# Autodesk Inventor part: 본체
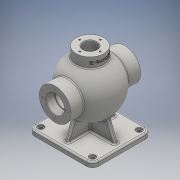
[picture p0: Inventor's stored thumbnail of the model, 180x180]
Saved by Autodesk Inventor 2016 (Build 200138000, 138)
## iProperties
Created: 2017-01
Part Number: 본체
Material: 일반
Document SubType Name: Modeling
Designer: Administrator
Density: 1 g/cm^3
Appearance: 기본값
Author: Administrator
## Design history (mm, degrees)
sketch "스케치1"
  geometry: L1 (-62.5, 57.5)-(62.5, 57.5); L2 (62.5, 57.5)-(62.5, -57.5); L3 (62.5, -57.5)-(-62.5, -57.5); L4 (-62.5, -57.5)-(-62.5, 57.5); 1 further point
  constraints: 8 end point, 2 parallel, 1 horizontal, 1 perpendicular
  dimensions: "d0" = 125 distance of L1.start L1.end; "d1" = 115 distance of L1.end L2.end; "d2" = 57.5 distance from line of point (0, 0) L1; "d3" = 62.5 distance from line of point (0, 0) L4
extrude "돌출1" new body sketch "스케치1" distance "d4" = 10; taper "d5" = 0 deg
fillet "모깎기1" dims "d6" = 12
sketch "스케치2"
  geometry: A1 r 12 centre (-50.5, 45.5) between (-50.5, 57.5) and (-62.5, 45.5) reference; 2 further points
  constraints: 1 coincident
hole "구멍1" sketch "스케치2" at (-50.5, 45.5) diameter "d7" = 8; stored, may be unused: countersink angle "d11" = 90 deg, drill point angle "d13" = 118 deg; dims "d8" = 6, "d9" = 12, "d10" = 3, "d12" = 8
sketch "스케치4"
  geometry: L1 (-45.5, 0)-(45.5, 0) reference; L2 (0, 85)-(68, 85); L3 (68, 85)-(68, 116); L4 (68, 116)-(42.988, 116); L5 (0, 85)-(-68, 85); L6 (-68, 85)-(-68, 116); L7 (-68, 116)-(-42.988, 116); A1 r 53 centre (0, 85) between (42.988, 116) and (-42.988, 116); 1 further point
  constraints: 12 end point, 2 horizontal, 2 parallel, 2 perpendicular, 2 point on circle, 1 centre point
revolve "회전1" sketch "스케치4" stored, may be unused: angle "d26" = 90 deg
sketch "스케치5"
  geometry: L1 (-45.5, 10)-(45.5, 10) reference; L2 (25.353, 64.816)-(47.5, 10); L3 (57.5, 0)-(57.5, 10) reference; L4 (-51.5, 10)-(-39.5, 10) reference; L5 (-47.5, 10)-(-25.353, 64.816); L6 (-57.5, 10)-(-57.5, 0) reference; L7 (-25.353, 64.816)-(25.353, 64.816); L8 (-47.5, 10)-(47.5, 10)
  constraints: 8 end point, 2 horizontal, 2 point on line
  dimensions: "d45" = 10 distance from line of L3 L2.end; "d46" = 22 deg angle of L3 L2; "d47" = 22 deg angle of L6 L5; "d48" = 10 distance from line of L6 L5.start
fillet "모깎기4" dims "d38" = 3
extrude "돌출3" join sketch "스케치5" stored distance "d49" = 8; taper "d50" = 0 deg
sketch "스케치7"
  geometry: L1 (-50.5, 10)-(50.5, 10) reference; L2 (62.5, 10)-(62.5, 0) reference; L3 (50.5, 10)-(-50.5, 10) reference; L4 (-37.379, 47.426)-(-52.5, 10); L5 (-62.5, 0)-(-62.5, 10) reference; L6 (37.379, 47.426)-(52.5, 10); A1 r 53 centre (0, 85) between (4, 32.151) and (-4, 32.151) reference; 1 further point
  constraints: 4 end point, 2 point on circle, 2 point on line
  dimensions: "d52" = 10 distance from line of L5 L4.end; "d53" = 22 deg angle of L5 L4; "d55" = 10 distance from line of L2 L6.end; "d57" = 22 deg angle of L6 L2
feature "리브2" dims "d64" = 1, "d65" = 8, "d66" = 0, "d67" = 0, "d68" = 1, "d69" = 1
feature "리브3" dims "d70" = 1, "d71" = 8, "d72" = 0, "d73" = 0, "d74" = 1, "d75" = 1
fillet "모깎기5" dims "d76" = 3
fillet "모깎기6" dims "d77" = 3
fillet "모깎기7" dims "d78" = 3
sketch "스케치8"
  geometry: L1 (-68, 54)-(-68, 116) reference; L2 (68, 85)-(-68, 85); L3 (-68, 85)-(-68, 102.5); L4 (68, 102.5)-(68, 85); L5 (45.5, 0)-(-45.5, 0) reference; L6 (39.278, 102.5)-(68, 102.5); L7 (-50.25, 102.5)-(-50.25, 103.5); L8 (-50.25, 103.5)-(-52, 103.5); L9 (-52, 103.5)-(-52, 102.5); L10 (-68, 102.5)-(-52, 102.5); L11 (-50.25, 102.5)-(-39.278, 102.5); A1 r 43 centre (0, 85) between (39.278, 102.5) and (-39.278, 102.5); 1 further point
  constraints: 18 end point, 4 parallel, 2 horizontal, 2 point on circle, 2 vertical, 1 centre point, 1 midpoint, 1 perpendicular, 1 point on line
  dimensions: "d79" = 85 distance between parallel lines of L5 L2; "d81" = 86 diameter of A1; "d85" = 16 distance of L3.end L9.end; "d86" = 1.75 distance of L7.end L8.end; "d87" = 136 distance of L2.start L2.end; "d143" = 17.5 distance between parallel lines of L2 L6
revolve "회전2" sketch "스케치8" stored, may be unused: angle "d82" = 90 deg
chamfer "모따기1" distance "d88" = 1; stored, may be unused: second distance "d89" = 2, angle "d90" = 45 deg
sketch "스케치9"
  geometry: 2 further points
hole "구멍2" sketch "스케치9" at (0, -22.5) diameter "d92" = 3.242; stored, may be unused: countersink angle "d96" = 90 deg, drill point angle "d98" = 118 deg; dims "d93" = 12, "d94" = 12, "d95" = 3, "d97" = 15
sketch "스케치10"
  geometry: 2 further points
hole "구멍3" sketch "스케치10" at (0, 24) diameter "d103" = 3.242; stored, may be unused: countersink angle "d107" = 90 deg, drill point angle "d109" = 118 deg; dims "d104" = 16, "d105" = 12, "d106" = 3, "d108" = 19
node "작업 평면1"
sketch "스케치11"
  geometry: C1 r 27 at (0, 0); 1 further point
  constraints: 1 centre point, 1 coincident
  dimensions: "d114" = 54 diameter of C1
extrude "돌출4" join sketch "스케치11" stored distance "d115" = 8; taper "d116" = 0 deg
sketch "스케치12"
  geometry: C1 r 13 at (0, 0); 1 further point
  constraints: 1 centre point, 1 coincident
  dimensions: "d117" = 26 diameter of C1
extrude "돌출5" cut sketch "스케치12" distance "d118" = 58.75; taper "d119" = 0 deg
sketch "스케치13"
  geometry: 2 further points
hole "구멍4" sketch "스케치13" at (0, 20) diameter "d121" = 3.242; stored, may be unused: countersink angle "d125" = 90 deg, drill point angle "d127" = 118 deg; dims "d122" = 9, "d123" = 12, "d124" = 3, "d126" = 11
node "작업 평면2"
sketch "스케치15"
  geometry: L1 (-20.81, 138.177)-(20.81, 138.177); L2 (20.81, 138.177)-(20.81, 141.823); L3 (20.81, 141.823)-(-20.81, 141.823); L4 (-20.81, 141.823)-(-20.81, 138.177); L5 (27, 150)-(-27, 150) reference; 4 further points
  constraints: 2 midpoint, 2 other
  dimensions: "d135" = 27 horizontal distance of point (0, 140) L5.end; "d142" = 10 distance from line of L5 point (20.81, 140)
feature "엠보싱1" sketch "스케치15" dims "d4" = 10, "d136" = 0.5, "d137" = 0
fillet "모깎기8" dims "d138" = 3
chamfer "모따기2" distance "d139" = 1; stored, may be unused: second distance "d140" = 2, angle "d141" = 45 deg
node "솔리드1"
pattern_linear "직사각형 패턴1" dims "d16" = 101, "d19" = 91
pattern_circular "원형 패턴2" dims angle "d100" = 360 deg
pattern_circular "원형 패턴3" dims angle "d111" = 360 deg
pattern_circular "원형 패턴4" dims angle "d129" = 360 deg
other parameters: "d80" = 17.5, "d131" = 92.75
